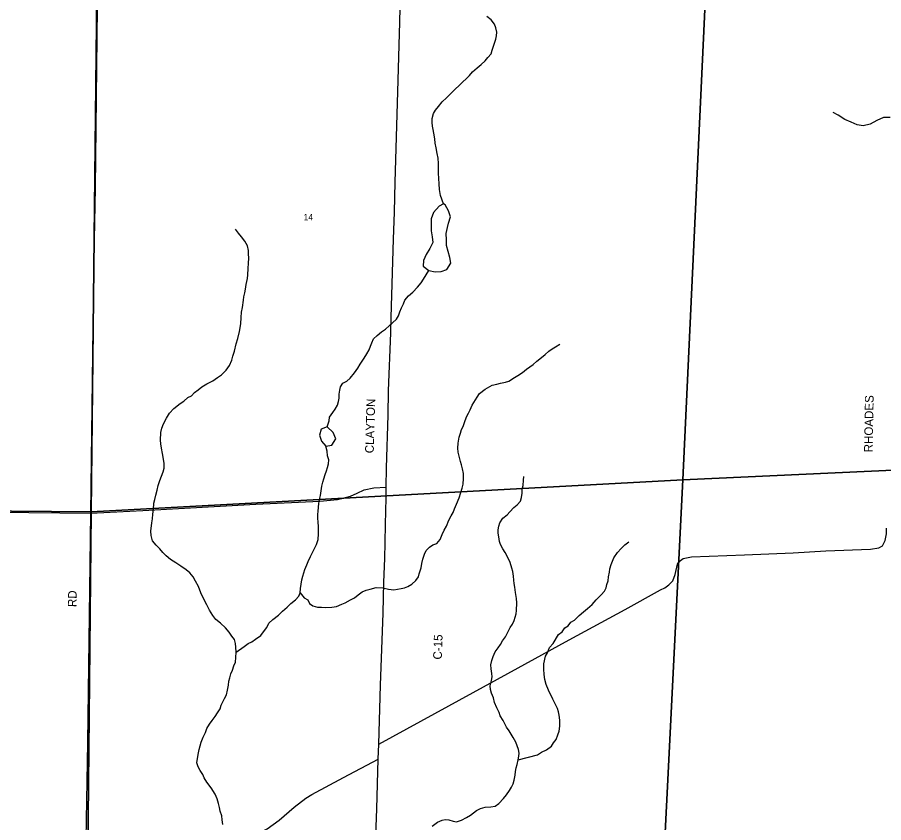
# Model space of a CAD drawing. Extents: x 1312308 to 1684953, y 460642 to 865172.
# Drawn here: x 1432056 to 1439573, y 622000 to 628989 of the extents above; entities that cross this region are included whole.
import ezdxf

# ---------------------------------------------------------------- set-up
doc = ezdxf.new("R2010")
doc.units = 0
for name, color, linetype in [('GM_X_County_Road', 7, 'Continuous'), ('GM_X_County_Road_Text', 7, 'Continuous'), ('GM_X_Minor_Lake', 7, 'Continuous'), ('GM_X_Minor_River', 7, 'Continuous'), ('GM_X_Section', 7, 'Continuous'), ('GM_X_Section_Text', 7, 'Continuous'), ('GM_X_Township_Road', 7, 'Continuous'), ('GM_X_Township_Road_Text', 7, 'Continuous')]:
    doc.layers.add(name, color=color, linetype=linetype)

msp = doc.modelspace()

# ---------------------------------------------------------------- linework, layer by layer
at = {"layer": 'GM_X_County_Road'}
for points in [[(1435192.8, 622682.7), (1435206, 623192.2), (1435230.5, 623817.5), (1435236.9, 624086.9), (1435244.4, 624292.4), (1435247, 624432.2), (1435250.8, 624588.5), (1435256.1, 624820), (1435256.6, 624911.8), (1435259.3, 625078.3), (1435274.2, 625535.5), (1435278, 625746.3), (1435296.1, 626251), (1435299.3, 626384.4), (1435319.6, 627062.5), (1435327.6, 627298.9), (1435334, 627557.6), (1435357.5, 628343), (1435372.2, 628849.3), (1435373.5, 628944.8), (1435382, 629206.8)], [(1435185.7, 622550.4), (1435192.8, 622682.7), (1435800.2, 623014.2), (1436310.9, 623295.7), (1436842.9, 623587.7), (1437329, 623851.2), (1437636.2, 624020.6), (1437675, 624039.3), (1437709.6, 624063.9), (1437744.1, 624100.3), (1437764.6, 624153.9), (1437785.1, 624244.9), (1437798.5, 624267.9), (1437833, 624293.6), (1437905, 624306.3), (1438366.4, 624323.2), (1438786.9, 624343), (1439070.5, 624358.5), (1439459.2, 624373.3), (1439529.7, 624383.9), (1439563.6, 624402.7), (1439585.5, 624448.8), (1439596.1, 624505.9), (1439596.1, 624556.7)], [(1432008, 620675), (1432161.2, 620775.1), (1432235.4, 620817.5), (1432325.6, 620864.9), (1432638.3, 621019.8), (1432747.9, 621071.3), (1432902, 621168.1), (1433172.7, 621335.8), (1433449.5, 621501.1), (1433543.1, 621562), (1433689.7, 621649.8), (1433935.3, 621799.7), (1434096.8, 621881.7), (1434224.1, 621946.4), (1434326.7, 622023), (1434457.3, 622135.5), (1434558.2, 622213.8), (1434610.5, 622243.9), (1434884.9, 622391.8), (1435185.7, 622550.4)]]:
    msp.add_lwpolyline(points, dxfattribs=at)
at = {"layer": 'GM_X_Minor_Lake'}
for points in [[(1435752.7, 627369), (1435717, 627349.5), (1435665.8, 627296.5), (1435646.6, 627240.8), (1435647.6, 627190.7), (1435646.4, 627136.6), (1435655.4, 627084.3), (1435660.4, 627034), (1435635.2, 626982.5), (1435602.1, 626931.1), (1435579, 626879.5), (1435575.9, 626829.4), (1435627.3, 626792.2), (1435681.1, 626779.1), (1435733.4, 626784), (1435783.8, 626800.9), (1435817, 626854.3), (1435808, 626904.6), (1435793.1, 626957), (1435780.1, 627007.4), (1435779.1, 627057.5), (1435776.2, 627111.7), (1435787.3, 627163.6), (1435796.1, 627201.5)], [(1435796.1, 627201.5), (1435813.3, 627257.2), (1435798.4, 627309.7), (1435769.3, 627360.4), (1435752.7, 627369)], [(1434796.2, 625384.9), (1434745.1, 625436.2), (1434692.6, 625415.2), (1434677.5, 625363.4), (1434696.4, 625310.9), (1434733.6, 625268)], [(1434733.6, 625268), (1434783.9, 625274.9), (1434819.1, 625330.3), (1434796.2, 625384.9)]]:
    msp.add_lwpolyline(points, dxfattribs=at)
at = {"layer": 'GM_X_Minor_River'}
for points in [[(1435752.7, 627369), (1435728.6, 627442.9), (1435718.6, 627493.6), (1435715.6, 627543.8), (1435712.6, 627590), (1435711.5, 627636.2), (1435710.2, 627670.4), (1435711.2, 627720.5), (1435708.1, 627766.7), (1435698.9, 627807), (1435689.9, 627855.3), (1435682.7, 627895.6), (1435677.5, 627933.8), (1435670.5, 627984.1), (1435663.1, 628014.4), (1435657.7, 628044.6), (1435654.3, 628074.7), (1435655, 628110.8), (1435665.9, 628152.8), (1435684.6, 628182.5), (1435709.3, 628216.2), (1435742.2, 628255.7), (1435779, 628289.1), (1435822, 628332.5), (1435856.8, 628368), (1435885.4, 628393.5), (1435920.3, 628429), (1435950.9, 628454.5), (1435979.6, 628484.1), (1436004.3, 628515.7), (1436045.1, 628551.1), (1436081.8, 628578.5), (1436114.5, 628610), (1436139.2, 628639.7), (1436166, 628673.3), (1436176.6, 628703.2), (1436193.7, 628755), (1436208.6, 628798.9), (1436213.2, 628826.9), (1436215.9, 628861), (1436208.7, 628897.2), (1436195.3, 628929.6), (1436165.9, 628966.2), (1436128.5, 628997)], [(1439628.4, 628118.8), (1439572.3, 628120), (1439513.6, 628093.2), (1439456.8, 628060.4), (1439396.4, 628047.7), (1439342.4, 628056.8), (1439290.8, 628080), (1439235.1, 628103.2), (1439177.7, 628140.5), (1439136.1, 628163.5)], [(1433818.3, 623730.5), (1433778.8, 623763.3), (1433753.5, 623798), (1433724.3, 623844.7), (1433699.2, 623889.3), (1433668.4, 623952.1), (1433647.2, 623994.7), (1433628.3, 624049.3), (1433603.1, 624095.9), (1433581.8, 624132.4), (1433552.5, 624169.1), (1433520.9, 624195.8), (1433473.4, 624226.8), (1433431.9, 624253.7), (1433384.4, 624284.7), (1433348.9, 624315.4), (1433319.4, 624346.1), (1433294, 624376.7), (1433260.5, 624409.4), (1433229.2, 624446.1), (1433218.1, 624492.5), (1433214.9, 624530.7), (1433224.4, 624602.8), (1433229.1, 624636.9), (1433231.9, 624677), (1433236.8, 624717.1), (1433241.9, 624773.2), (1433248.6, 624805.2), (1433257.4, 624843.2), (1433270.3, 624887.1), (1433279.2, 624927.1), (1433292.1, 624969), (1433321.7, 625044.8), (1433330.4, 625076.7), (1433329.3, 625120.9), (1433316.9, 625203.4), (1433307.9, 625249.8), (1433300.6, 625288.1), (1433299.3, 625320.2), (1433300.6, 625386.4), (1433309.4, 625422.4), (1433324.2, 625462.3), (1433351.3, 625510), (1433376.3, 625553.7), (1433413.2, 625593.2), (1433468.2, 625636.3), (1433500.7, 625657.8), (1433535.5, 625689.3), (1433565.9, 625704.8), (1433594.6, 625734.3), (1433625.1, 625755.9), (1433655.7, 625781.4), (1433700.4, 625808.7), (1433753.1, 625835.8), (1433793.8, 625863.2), (1433828.4, 625886.6), (1433869.3, 625928), (1433896.2, 625967.7), (1433917.2, 626013.5), (1433926, 626049.4), (1433940.9, 626093.3), (1433954.2, 626155.3), (1433969.2, 626203.2), (1433984.5, 626263.1), (1433995.9, 626329.2), (1433999, 626385.3), (1434001.9, 626429.4), (1434008.8, 626471.4), (1434018.1, 626533.5), (1434022.7, 626563.5), (1434029.5, 626597.5), (1434036.1, 626629.5), (1434043, 626671.5), (1434052.1, 626721.5), (1434054.8, 626755.6), (1434057.9, 626809.7), (1434060.8, 626855.8), (1434063.7, 626897.9), (1434062.5, 626936), (1434061.1, 626966.2), (1434051.8, 627004.5), (1434030.6, 627045), (1434001.3, 627083.7), (1433975.9, 627116.3), (1433950.5, 627150.8)], [(1434745.1, 625436.2), (1434762.9, 625486.1), (1434765.5, 625518.2), (1434792.5, 625559.8), (1434815.1, 625589.5), (1434833.9, 625623.3), (1434842.6, 625655.2), (1434849.2, 625685.2), (1434849.9, 625717.3), (1434854.6, 625753.4), (1434859.2, 625783.4), (1434879.9, 625815.1), (1434916.4, 625832.5), (1434945, 625858.1), (1434982, 625903.6), (1435011, 625945.2), (1435031.7, 625979), (1435064.9, 626030.5), (1435089.7, 626068.2), (1435108.5, 626104), (1435119.1, 626133.9), (1435131.8, 626163.8), (1435146.6, 626199.6), (1435177.2, 626229.2), (1435216, 626260.6), (1435250.6, 626284), (1435281.2, 626311.6), (1435311.8, 626337.1), (1435344.6, 626368.6), (1435363.2, 626398.4), (1435376, 626434.3), (1435388.7, 626468.2), (1435405.5, 626502), (1435418.2, 626533.8), (1435449, 626571.4), (1435487.8, 626602.8), (1435526.8, 626648.3), (1435559.6, 626683.8), (1435580.4, 626717.5), (1435627.3, 626792.2)], [(1434509.7, 623994.9), (1434544.9, 623950.1), (1434576.7, 623935.5), (1434592, 623903.1), (1434619.7, 623882.5), (1434661.6, 623871.7), (1434695.7, 623871), (1434733.7, 623868.3), (1434785.9, 623869.4), (1434826.2, 623876.7), (1434872.7, 623895.9), (1434901, 623907.4), (1434945.7, 623934.7), (1434980.2, 623952.2), (1435012.8, 623977.7), (1435049.4, 624003.1), (1435083.8, 624018.5), (1435118.1, 624027.9), (1435168.5, 624041.1), (1435226.6, 624038), (1435276.5, 624027), (1435322.6, 624022.2), (1435354.7, 624025.6), (1435386.9, 624031), (1435415.2, 624038.6), (1435445.5, 624050), (1435480, 624069.5), (1435514.7, 624101), (1435535.5, 624132.7), (1435544, 624160.7), (1435559.1, 624210.6), (1435565.9, 624248.6), (1435574.7, 624286.6), (1435587.7, 624330.6), (1435602.3, 624362.4), (1435631, 624392), (1435661.5, 624411.5), (1435695.9, 624422.9), (1435724.6, 624456.5), (1435741.6, 624502.4), (1435760.4, 624538.2), (1435781.2, 624574), (1435800.3, 624625.8), (1435821.1, 624663.6), (1435837.7, 624691.4), (1435848.4, 624723.3), (1435867.3, 624765.2), (1435888.5, 624819), (1435905.5, 624866.8), (1435916.3, 624902.8), (1435923, 624936.8), (1435928, 624986.9), (1435926.9, 625031.1), (1435919.7, 625069.4), (1435910.4, 625105.7), (1435901, 625135.9), (1435891.7, 625170.2), (1435880.6, 625216.6), (1435877.2, 625248.8), (1435880.2, 625292.9), (1435889.2, 625344.9), (1435900, 625378.9), (1435910.6, 625410.8), (1435925.3, 625438.6), (1435940.4, 625490.5), (1435957.1, 625526.4), (1435969.7, 625554.2), (1435986.4, 625584.1), (1436003.3, 625623.9), (1436044.8, 625693.4), (1436065.5, 625723.1), (1436114.4, 625762.4), (1436175.3, 625797.4), (1436217.6, 625806.6), (1436247.8, 625814.1), (1436292.2, 625823.3), (1436320.4, 625830.8), (1436369.2, 625862.1), (1436397.6, 625879.6), (1436438.3, 625906.9), (1436473, 625934.4), (1436503.5, 625955.9), (1436532, 625977.5), (1436562.7, 626005), (1436605.4, 626036.4), (1436636.1, 626063.9), (1436668.7, 626091.4), (1436697.2, 626112.9), (1436725.6, 626128.5), (1436764.2, 626151.8)], [(1433953.5, 623479), (1434024.8, 623529.9), (1434059.4, 623555.4), (1434091.8, 623568.8), (1434122.3, 623592.4), (1434169.1, 623625.7), (1434191.8, 623655.4), (1434220.7, 623693), (1434239.5, 623730.8), (1434274.3, 623764.3), (1434321.1, 623799.6), (1434356, 623837.1), (1434396.8, 623870.5), (1434429.5, 623902), (1434468.3, 623935.4), (1434499.1, 623967), (1434509.7, 623994.9), (1434514.4, 624031), (1434519.3, 624071.1), (1434526, 624107.1), (1434534.7, 624139.1), (1434551.9, 624197), (1434566.8, 624238.9), (1434579.4, 624266.8), (1434600.4, 624310.5), (1434623.4, 624356.3), (1434638.1, 624386.2), (1434652.7, 624414), (1434665.6, 624457.9), (1434670.6, 624506), (1434669.2, 624538.2), (1434667.8, 624566.3), (1434666.7, 624610.5), (1434663.3, 624640.7), (1434664, 624674.8), (1434666.6, 624704.9), (1434672, 624769), (1434678.7, 624805), (1434685.4, 624839), (1434692.3, 624881.1), (1434697.1, 624919.2), (1434707.9, 624955.1), (1434716.5, 624985), (1434727.3, 625023), (1434740, 625052.9), (1434748.6, 625082.8), (1434755.3, 625114.8), (1434758, 625148.9), (1434747.7, 625183.7), (1434744.5, 625223.9), (1434733.6, 625268)], [(1435839, 622012.1), (1435866.9, 622007.6), (1435909.3, 622020.9), (1435951.9, 622044.2), (1435988.5, 622065.6), (1436041.4, 622104.8), (1436075.9, 622124.3), (1436114.3, 622135.6), (1436164.5, 622138.7), (1436200.7, 622144.1), (1436235.3, 622167.5), (1436274.3, 622211), (1436301, 622240.7), (1436327.8, 622278.4), (1436344.5, 622308.2), (1436357.1, 622336.1), (1436365.8, 622370.1), (1436374.7, 622412.1), (1436379.4, 622444.2), (1436384, 622476.2), (1436392.6, 622504.2), (1436401.5, 622546.2), (1436408.1, 622576.2), (1436410.7, 622604.3), (1436403.4, 622636.6), (1436394, 622666.9), (1436380.6, 622699.3), (1436357.3, 622739.9), (1436322.4, 622796.8), (1436301, 622829.3), (1436272.1, 622886.1), (1436246.8, 622926.7), (1436237.4, 622955), (1436216.2, 622995.6), (1436197.1, 623044.1), (1436187.9, 623082.4), (1436170.7, 623124.9), (1436161.3, 623157.2), (1436159.9, 623187.4), (1436168.9, 623233.4), (1436175.6, 623265.4), (1436174.2, 623295.6), (1436166.9, 623333.9), (1436165.7, 623370.1), (1436172.5, 623408.1), (1436185.2, 623442), (1436202.1, 623481.9), (1436226.9, 623517.6), (1436247.5, 623545.3), (1436266.2, 623577.1), (1436293, 623612.8), (1436311.9, 623654.6), (1436332.8, 623694.4), (1436351.4, 623722.1), (1436368.1, 623754), (1436385.4, 623813.9), (1436388, 623842), (1436389.3, 623908.2), (1436386.1, 623946.4), (1436379.1, 623998.8), (1436372.1, 624045.1), (1436366.7, 624075.3), (1436363.2, 624103.5), (1436360, 624139.7), (1436354.8, 624179.9), (1436347.4, 624210.2), (1436332.3, 624258.7), (1436316.9, 624289.1), (1436287.9, 624343.8), (1436268.5, 624376.3), (1436247.2, 624412.8), (1436239.8, 624441.1), (1436232.5, 624479.4), (1436229.2, 624511.5), (1436227.8, 624541.7), (1436232.5, 624573.7), (1436243.1, 624601.6), (1436270, 624641.3), (1436306.7, 624670.8), (1436329.3, 624698.4), (1436364.1, 624733.9), (1436392.7, 624759.5), (1436421.4, 624789.1), (1436430.1, 624821.1), (1436434.9, 624859.1), (1436437.6, 624893.2), (1436444.3, 624927.2), (1436449.2, 624971.3), (1436451.9, 625003.4)], [(1436401.5, 622546.2), (1436568.9, 622589.3), (1436603.4, 622610.8), (1436646, 622632.1), (1436690.7, 622663.4), (1436709.4, 622693.2), (1436730, 622720.9), (1436746.9, 622762.8), (1436757.6, 622794.8), (1436764.5, 622836.8), (1436763.6, 622889.1), (1436756.4, 622933.4), (1436751, 622961.6), (1436741.6, 622989.9), (1436718.5, 623038.5), (1436701.1, 623073), (1436664.6, 623150), (1436643.6, 623200.6), (1436634.4, 623242.9), (1436627.3, 623287.3), (1436624.2, 623331.5), (1436625.2, 623379.7), (1436638.6, 623445.7), (1436657.3, 623475.5), (1436674.2, 623521.4), (1436705, 623555), (1436752.7, 623632.4), (1436783.3, 623656), (1436806.1, 623691.7), (1436834.5, 623709.2), (1436859.2, 623738.9), (1436891.7, 623756.4), (1436930.6, 623797.8), (1436969.4, 623831.3), (1437002.1, 623858.8), (1437042.9, 623892.2), (1437079.8, 623933.7), (1437122.8, 623977.1), (1437149.6, 624008.7), (1437164.2, 624038.5), (1437170.8, 624066.5), (1437181.5, 624098.5), (1437186.2, 624132.5), (1437193.1, 624174.6), (1437197.7, 624202.6), (1437208.5, 624240.5), (1437231.7, 624298.3), (1437262.8, 624344), (1437295.6, 624379.5), (1437328.3, 624411), (1437363, 624438.5)], [(1433840.6, 621984.6), (1433833.4, 622024.9), (1433830.2, 622061.1), (1433816.9, 622099.5), (1433809.6, 622131.8), (1433802.3, 622168.1), (1433791, 622206.5), (1433773.8, 622247), (1433736.9, 622303.9), (1433699.7, 622350.8), (1433676.4, 622389.4), (1433665, 622419.7), (1433641.7, 622454.3), (1433624.2, 622484.8), (1433615, 622521.1), (1433624.5, 622593.2), (1433633.3, 622635.3), (1433650.7, 622699.2), (1433667.6, 622743.1), (1433688.5, 622782.9), (1433701.3, 622818.8), (1433724.1, 622854.5), (1433746.8, 622886.3), (1433771.6, 622922), (1433792.3, 622953.7), (1433815.1, 622987.4), (1433825.8, 623019.4), (1433855, 623077.1), (1433869.7, 623109), (1433878.6, 623151), (1433889.5, 623193), (1433892.2, 623227.1), (1433898.8, 623257.1), (1433909.6, 623291), (1433924.3, 623324.9), (1433935.1, 623360.8), (1433947.8, 623392.7), (1433952.6, 623432.8), (1433953.5, 623479), (1433952.4, 623523.2), (1433949.1, 623555.4), (1433939.8, 623589.7), (1433918.3, 623620.2), (1433892.9, 623654.8), (1433861.6, 623691.5), (1433818.3, 623730.5)], [(1435655.6, 621969.3), (1435700.4, 622004.6), (1435740.9, 622021.9), (1435769.1, 622027.5), (1435799.1, 622024.9), (1435839, 622012.1)]]:
    msp.add_lwpolyline(points, dxfattribs=at)
at = {"layer": 'GM_X_Section'}
for points in [[(1427370.7, 630042.9), (1432755.4, 629989.2), (1432697.6, 624696.5), (1427168.8, 624743.3)], [(1432755.4, 629989.2), (1438061.9, 629925.2), (1437831.5, 624976.2), (1432697.6, 624696.5)], [(1438061.9, 629925.2), (1443469, 629861.6), (1443369.8, 625229.9), (1437831.5, 624976.2)], [(1437831.5, 624976.2), (1443369.8, 625229.9), (1443287.6, 619943.9), (1443265.9, 619262.4), (1437545.7, 619310.6)], [(1437831.5, 624976.2), (1437545.7, 619310.6), (1432643.4, 619381.8), (1432697.6, 624696.5)], [(1432697.6, 624696.5), (1432643.4, 619381.8), (1426939.4, 619468.3), (1427168.8, 624743.3)]]:
    msp.add_lwpolyline(points, close=True, dxfattribs=at)
at = {"layer": 'GM_X_Township_Road'}
for points in [[(1432694.8, 624686), (1432720.7, 626760.3), (1432734.3, 627508.1), (1432754.1, 629340.8), (1432762.5, 629986)], [(1432694.8, 624686), (1433146.3, 624709.4), (1434124.5, 624765.4), (1434681.1, 624789.2), (1434833.5, 624804.1), (1434884.5, 624816.7), (1434945.8, 624834.5), (1435004.8, 624860.8), (1435065.6, 624887.2), (1435148.1, 624905), (1435256.6, 624911.8)], [(1427163, 624758.3), (1428201.4, 624735.5), (1429036.5, 624727.9), (1430853.3, 624703), (1431884.2, 624695.4), (1432694.8, 624686)], [(1432638.3, 621019.8), (1432667.7, 622695.5), (1432694.8, 624686)], [(1435331.9, 614673.4), (1435201.8, 614934.9), (1435140.5, 615028.1), (1435118.1, 615083), (1435108.5, 615160.7), (1435105.7, 615781.9), (1435101.4, 616267.4), (1435095, 616814.8), (1435076.8, 616950.3), (1435062.4, 617097), (1435062.4, 617220.3), (1435067, 617670.1), (1435102, 619336.2), (1435108.3, 619596.7), (1435119.5, 620229.4), (1435137.6, 620943.3), (1435155.8, 621579.8), (1435164.3, 621807.6), (1435174.5, 622121.9), (1435185.7, 622550.4)]]:
    msp.add_lwpolyline(points, dxfattribs=at)

# ---------------------------------------------------------------- texts
at = {"layer": 'GM_X_County_Road_Text'}
for s, rotation, p in [('CLAYTON', 88.27721, (1435147.8, 625205.1)), ('C-15', 87.94233, (1435738.3, 623414.8))]:
    msp.add_text(s, height=75, rotation=rotation, dxfattribs=at).set_placement(p)
at = {"layer": 'GM_X_Section_Text'}
msp.add_text('14', height=55.25, rotation=0.00001, dxfattribs=at).set_placement((1434539.8, 627227.6))
at = {"layer": 'GM_X_Township_Road_Text'}
for s, rotation, p in [('RHOADES', 88.98733, (1439477.3, 625213.4)), ('RD', 89.01184, (1432569.3, 623870.5))]:
    msp.add_text(s, height=75, rotation=rotation, dxfattribs=at).set_placement(p)

doc.saveas('drawing.dxf')
